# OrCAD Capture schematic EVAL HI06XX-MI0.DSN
size A; title: EVAL HI06XX-MI0; rev: A0; note: 1
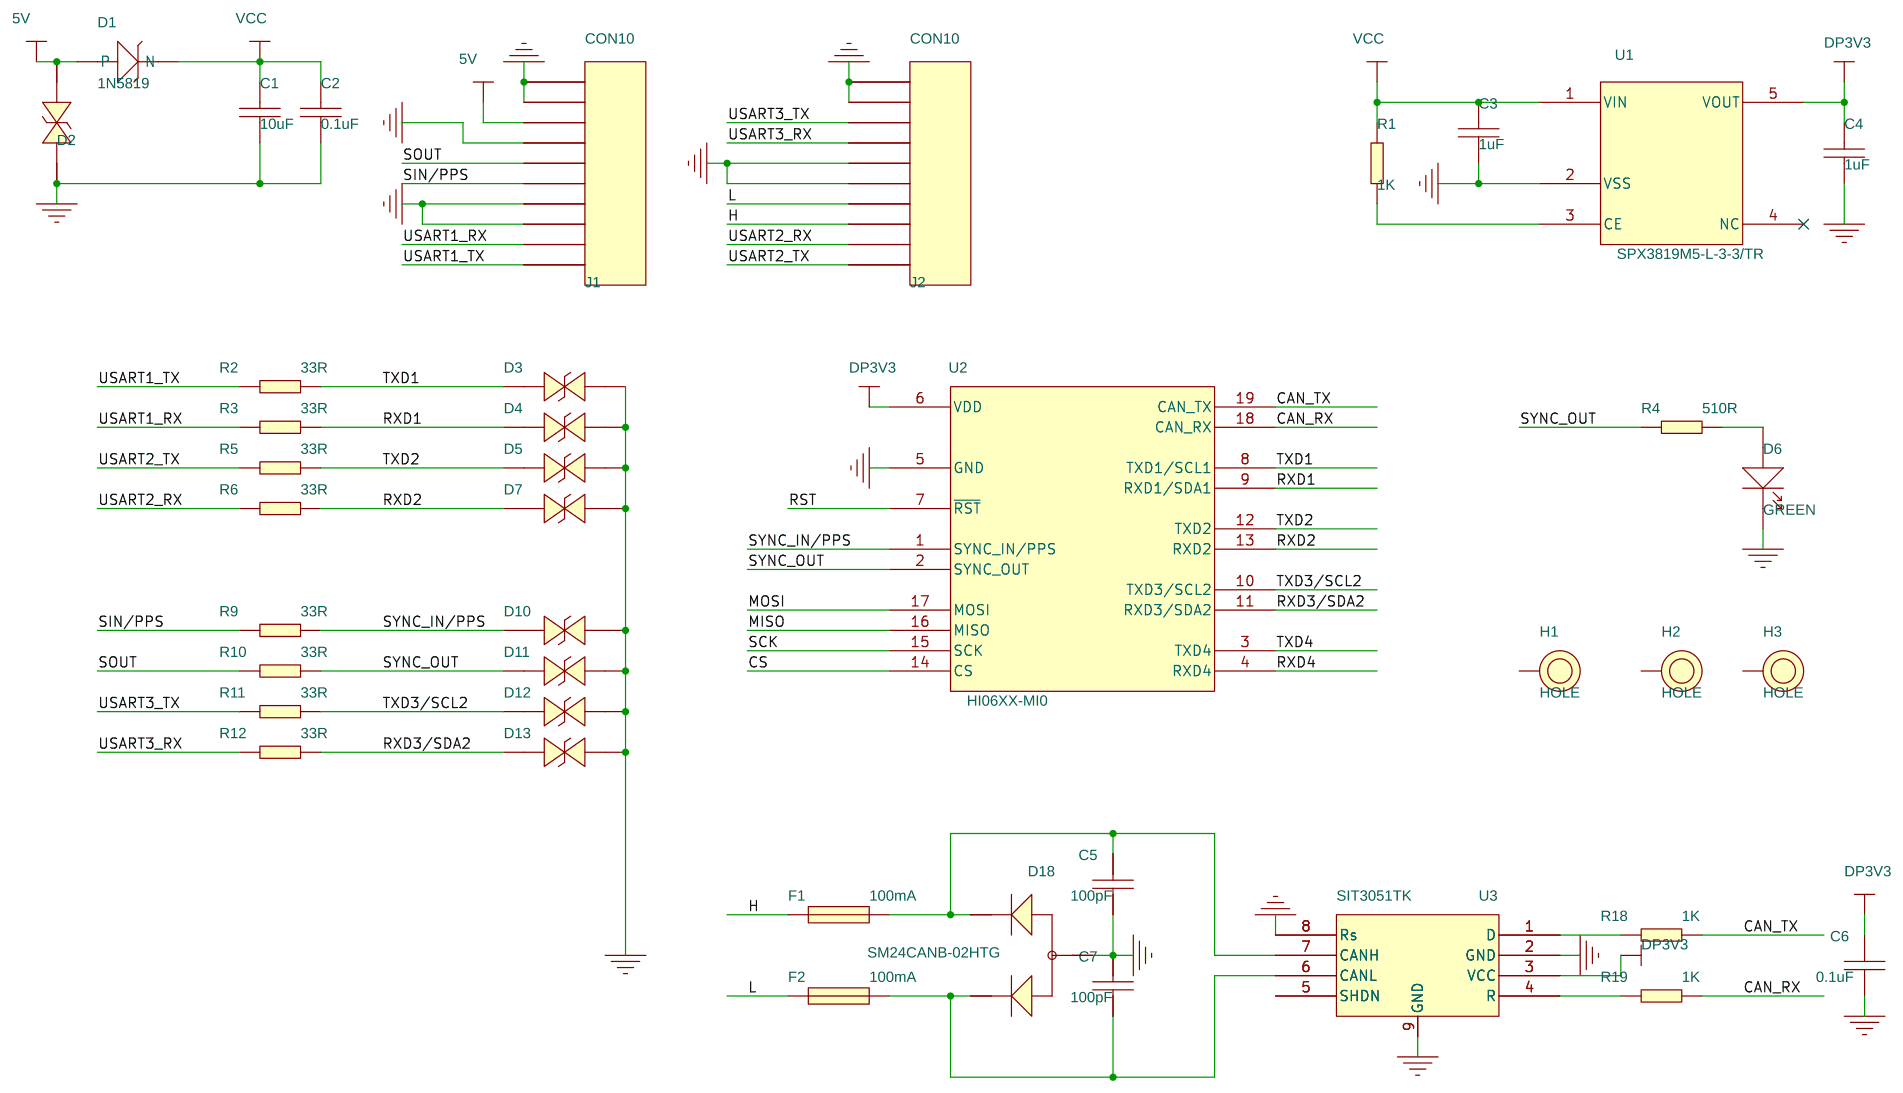
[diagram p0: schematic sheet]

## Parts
C1  10uF  [C0603]
C2  0.1uF  [C0402]
C3  1uF  [C0402]
C4  1uF  [C0402]
C5  100pF  [C0402]
C6  0.1uF  [C0402]
C7  100pF  [C0402]
D1  1N5819  [SOD123FL]
D2  SDD32A05L01  [SOD123FL]
D3  SBD52C05L01  [SOD-523]
D4  SBD52C05L01  [SOD-523]
D5  SBD52C05L01  [SOD-523]
D6  GREEN  [LED0402]
D7  SBD52C05L01  [SOD-523]
D10  SBD52C05L01  [SOD-523]
D11  SBD52C05L01  [SOD-523]
D12  SBD52C05L01  [SOD-523]
D13  SBD52C05L01  [SOD-523]
D18  SM24CANB-02HTG  [SOT23-3-0_95]
F1  100mA  [F0603]
F2  100mA  [F0603]
H1  HOLE  [HOLE-2-MM]
H2  HOLE  [HOLE-2-MM]
H3  HOLE  [HOLE-2-MM]
J1  CON10  [5015680807_1]
J2  CON10  [5015680807_1]
R1  1K  [R0402]
R2  33R  [R0402]
R3  33R  [R0402]
R4  510R  [R0402]
R5  33R  [R0402]
R6  33R  [R0402]
R9  33R  [R0402]
R10  33R  [R0402]
R11  33R  [R0402]
R12  33R  [R0402]
R18  1K  [R0402]
R19  1K  [R0402]
U1  SPX3819M5-L-3-3/TR  [SOT23-5-0_95]
U2  HI06XX-MI0  [HI06]
U3  SIT3051TK  [HVSON8]

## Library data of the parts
C1-C7 = Capacity_Nonpolarity
D1 = diode
D2-D5 D7 D10-D13 = DIODE_BI-DIR_TRIG
D6 = LED
D18 = BAT54A_SOT
F1 F2 = Fuse
H1-H3 = HOLE
J1 J2 = CON10
R1-R6 R9-R12 R18 R19 = Res
U1 = XC6210
U2 = HI05-MI0
U3 = SIT3051TK

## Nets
5V: D1.1(P) D2.2 J1.8
GND: C1.1 C2.1 C3.2 C4.1 C5.2 C6.2 C7.1 D2.1 D3.1 D4.1 D5.1 D6.2(-) D7.1 D10.1 D11.1 D12.1 D13.1 D18.3 J1.3 J1.4 J1.7 J1.9 J1.10 J2.5 J2.6 J2.9 J2.10 U1.2(VSS) U2.5(GND) U3.2(GND) U3.8(Rs) U3.9(GND)
VCC: C1.2 C2.2 C3.1 D1.2(N) R1.2 U1.1(VIN)
CAN_RX: R19.1 U2.18(CAN_RX)
CAN_TX: R18.1 U2.19(CAN_TX)
CS: U2.14(CS)
DP3V3: C4.2 C6.1 U1.5(VOUT) U2.6(VDD) U3.3(VCC)
H: F1.1 J2.3
L: F2.1 J2.4
MISO: U2.16(MISO)
MOSI: U2.17(MOSI)
RST: U2.7(~{RST})
RXD1: D4.2 R3.1 U2.9(RXD1/SDA1)
RXD2: D7.2 R6.1 U2.13(RXD2)
RXD3/SDA2: D13.2 R12.1 U2.11(RXD3/SDA2)
RXD4: U2.4(RXD4)
SCK: U2.15(SCK)
SIN/PPS: J1.5 R9.2
SOUT: J1.6 R10.2
SYNC_IN/PPS: D10.2 R9.1 U2.1(SYNC_IN/PPS)
SYNC_OUT: D11.2 R4.1 R10.1 U2.2(SYNC_OUT)
TXD1: D3.2 R2.1 U2.8(TXD1/SCL1)
TXD2: D5.2 R5.1 U2.12(TXD2)
TXD3/SCL2: D12.2 R11.1 U2.10(TXD3/SCL2)
TXD4: U2.3(TXD4)
USART1_RX: J1.2 R3.2
USART1_TX: J1.1 R2.2
USART2_RX: J2.2 R6.2
USART2_TX: J2.1 R5.2
USART3_RX: J2.7 R12.2
USART3_TX: J2.8 R11.2
N2198535: D6.1(+) R4.2
N2224750: R1.1 U1.3(CE)
N2242059: C5.1 D18.1 F1.2 U3.7(CANH)
N2242241: R18.2 U3.1(D)
N2242331: C7.2 D18.2 F2.2 U3.6(CANL)
N2242381: R19.2 U3.4(R)

Not connected (* = marked no-connect by the designer): H1 1; H2 1; H3 1; U1 4(NC)*; U3 5(SHDN)
